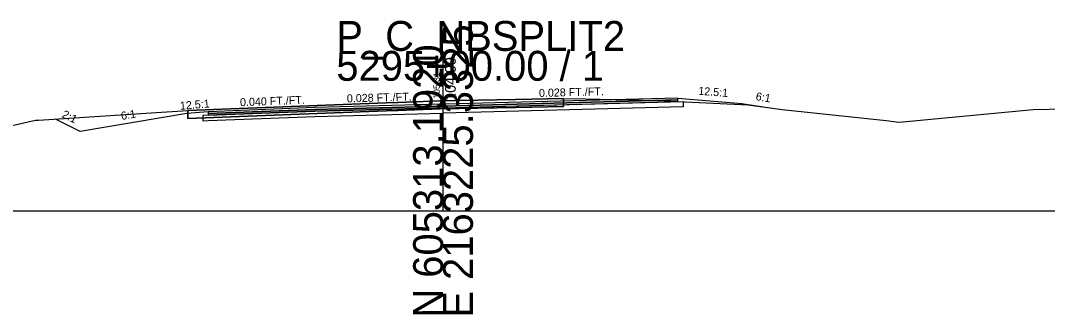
# Model space of a CAD drawing. Extents: x -26 to 1303, y -10 to 12038.
# Drawn here: x 110.4 to 206.6, y 7990.3 to 8017.8 of the extents above; entities that cross this region are included whole.
import ezdxf

# ---------------------------------------------------------------- set-up
doc = ezdxf.new("R2010")
doc.units = 0
for name, color, linetype in [('RD_GPK_XS_Cell', 7, 'Continuous'), ('RD_XS_Base', 7, 'Continuous'), ('RD_XS_ExGround', 7, 'Continuous'), ('RD_XS_ExPaveRet', 7, 'Continuous'), ('RD_XS_Greenside', 7, 'Continuous'), ('RD_XS_Pave', 7, 'Continuous'), ('RD_XS_PaveOvlay_CP', 7, 'Continuous'), ('RD_XS_TieSlope', 7, 'Continuous'), ('RD_XS_TX_Elev_EX', 7, 'Continuous'), ('RD_XS_TX_Elev_PR', 7, 'Continuous'), ('RD_XS_TX_ShdSlope', 7, 'Continuous'), ('RD_XS_TX_Slope', 7, 'Continuous')]:
    doc.layers.add(name, color=color, linetype=linetype)

msp = doc.modelspace()

# ---------------------------------------------------------------- linework, layer by layer
at = {"layer": 'RD_GPK_XS_Cell'}
for p, q in [((150, 8000), (150, 8015)), ((0, 8000), (150, 8000)), ((150, 8000), (300, 8000))]:
    msp.add_line(p, q, dxfattribs=at)
at = {"layer": 'RD_XS_Base'}
for p, q in [((150, 8009.675), (138, 8009.363)), ((150, 8009.675), (172.5, 8010.26)), ((150, 8009.175), (150, 8009.834)), ((150, 8009.834), (150, 8009.834)), ((150, 8009.834), (150, 8009.834)), ((150, 8009.834), (150, 8009.675)), ((172.5, 8009.76), (150, 8009.175)), ((150, 8009.675), (150, 8009.675)), ((150, 8009.175), (150, 8009.675)), ((150, 8009.675), (150, 8009.675)), ((150, 8009.675), (150, 8009.675)), ((172, 8010.247), (172, 8010.247)), ((172, 8010.247), (172, 8010.247)), ((172, 8010.247), (172, 8010.247)), ((172, 8009.747), (172, 8009.747)), ((172, 8009.747), (172, 8009.747)), ((172.5, 8010.26), (172.5, 8009.76)), ((172.5, 8010.227), (172.5, 8010.227)), ((128, 8008.963), (127.5, 8008.943)), ((127.5, 8008.943), (127.5, 8008.943)), ((127.5, 8008.943), (127.5, 8008.443)), ((138, 8009.363), (128, 8008.963)), ((128, 8008.963), (128, 8008.963)), ((128, 8008.463), (138, 8008.863)), ((138, 8009.363), (138, 8009.363)), ((138, 8008.863), (150, 8009.175)), ((138, 8008.863), (138, 8008.863)), ((150, 8009.175), (150, 8009.175)), ((127.5, 8008.443), (128, 8008.463)), ((128, 8008.463), (128, 8008.463))]:
    msp.add_line(p, q, dxfattribs=at)
at = {"layer": 'RD_XS_ExGround'}
msp.add_lwpolyline([(106.167, 8007.217), (111.821, 8008.514), (112.089, 8008.497), (123.111, 8009.221), (124.614, 8009.316), (126.103, 8009.423), (144.682, 8010.133), (145.738, 8010.173), (145.8, 8010.173), (146.591, 8010.201), (149.721, 8010.309), (156.814, 8010.456), (161.286, 8010.541), (163.392, 8010.52), (170.073, 8010.344), (178.592, 8009.952), (181.759, 8009.501), (191.508, 8008.463), (192.706, 8008.335), (193.72, 8008.429), (205.301, 8009.501), (211.3, 8009.648)], dxfattribs=at)
at = {"layer": 'RD_XS_ExPaveRet'}
for points in [[(161.286, 8010.541), (161.286, 8010.541), (161.286, 8009.791), (156.814, 8009.706), (156.814, 8009.706), (149.721, 8009.559), (149.721, 8009.559), (149.721, 8009.559), (146.591, 8009.451), (146.591, 8009.451), (145.8, 8009.423), (145.738, 8009.423), (145.738, 8009.423), (144.682, 8009.383), (144.682, 8009.383), (126.103, 8008.673), (126.103, 8008.673), (126.103, 8009.423), (126.103, 8009.423), (126.103, 8009.423), (144.682, 8010.134), (144.682, 8010.134), (145.738, 8010.173), (145.738, 8010.173), (145.8, 8010.173), (146.591, 8010.201), (146.591, 8010.201), (149.721, 8010.309), (149.721, 8010.309), (149.721, 8010.309), (156.814, 8010.457), (156.814, 8010.457), (161.286, 8010.541)], [(156.814, 8010.457), (149.721, 8010.309), (146.591, 8010.201), (145.8, 8010.173), (145.738, 8010.173), (144.682, 8010.134), (126.103, 8009.423), (126.103, 8008.673), (144.682, 8009.383), (145.738, 8009.423), (145.8, 8009.423), (146.591, 8009.451), (149.721, 8009.559), (156.814, 8009.706), (161.286, 8009.791), (161.286, 8010.541), (156.814, 8010.457)]]:
    msp.add_lwpolyline(points, dxfattribs=at)
at = {"layer": 'RD_XS_Greenside'}
for p, q in [((178, 8010.085), (180.03, 8009.747)), ((126, 8009.121), (116, 8007.454)), ((116, 8007.454), (113.702, 8008.603))]:
    msp.add_line(p, q, dxfattribs=at)
at = {"layer": 'RD_XS_Pave'}
for p, q in [((172, 8010.565), (150, 8009.993)), ((172, 8010.406), (172, 8010.565)), ((172, 8010.565), (172, 8010.565)), ((172, 8010.565), (172, 8010.565)), ((172, 8010.565), (172, 8010.565)), ((138, 8009.681), (128, 8009.281)), ((150, 8009.993), (138, 8009.681)), ((138, 8009.522), (150, 8009.834)), ((150, 8009.834), (138, 8009.522)), ((138, 8009.681), (138, 8009.681)), ((138, 8009.363), (150, 8009.675)), ((172, 8010.406), (150, 8009.834)), ((150, 8009.834), (172, 8010.406)), ((150, 8009.675), (172, 8010.247)), ((150, 8009.993), (150, 8009.993)), ((150, 8009.834), (150, 8009.834)), ((150, 8009.834), (150, 8009.834)), ((150, 8009.834), (150, 8009.675)), ((150, 8009.834), (150, 8009.834)), ((150, 8009.675), (150, 8009.834)), ((150, 8009.834), (150, 8009.834)), ((150, 8009.834), (150, 8009.834)), ((150, 8009.675), (150, 8009.675)), ((150, 8009.675), (150, 8009.675)), ((172, 8010.247), (172, 8010.406)), ((172, 8010.406), (172, 8010.406)), ((172, 8010.406), (172, 8010.406)), ((172, 8010.406), (172, 8010.406)), ((172, 8010.406), (172, 8010.406)), ((172, 8010.406), (172, 8010.406)), ((172, 8010.247), (172, 8010.247)), ((172, 8010.247), (172, 8010.247)), ((128, 8009.122), (138, 8009.522)), ((138, 8009.522), (128, 8009.122)), ((128, 8008.963), (138, 8009.363)), ((128, 8009.281), (128, 8009.281)), ((128, 8009.281), (128, 8009.122)), ((128, 8009.122), (128, 8009.122)), ((128, 8009.122), (128, 8008.963)), ((138, 8009.522), (138, 8009.522)), ((138, 8009.522), (138, 8009.522)), ((138, 8009.363), (138, 8009.363))]:
    msp.add_line(p, q, dxfattribs=at)
at = {"layer": 'RD_XS_PaveOvlay_CP'}
for p, q in [((172, 8010.565), (150, 8009.993)), ((172, 8010.565), (172, 8010.565)), ((172, 8010.565), (172, 8010.565)), ((138, 8009.681), (128, 8009.281)), ((150, 8009.993), (138, 8009.681)), ((138, 8009.681), (138, 8009.681)), ((150, 8009.993), (150, 8009.993))]:
    msp.add_line(p, q, dxfattribs=at)
at = {"layer": 'RD_XS_TieSlope'}
for p, q in [((172, 8010.565), (178, 8010.085)), ((128, 8009.281), (126, 8009.121))]:
    msp.add_line(p, q, dxfattribs=at)

# ---------------------------------------------------------------- texts
at = {"layer": 'RD_GPK_XS_Cell'}
for s, p in [('P_C_NBSPLIT2', (140, 8015)), ('5295+00.00 / 1', (140, 8012.2))]:
    msp.add_text(s, height=2.8, dxfattribs=at).set_placement(p)
for s, p in [('E 2163225.3325', (152.8, 7990)), ('N 605313.1920', (150, 7990))]:
    msp.add_text(s, height=2.8, rotation=90, dxfattribs=at).set_placement(p)
at = {"layer": 'RD_XS_TX_Elev_EX'}
msp.add_text('105.31', height=0.6, rotation=90, dxfattribs=at).set_placement((149.697, 8010.531))
at = {"layer": 'RD_XS_TX_Elev_PR'}
msp.add_text('104.99', height=1, rotation=90, dxfattribs=at).set_placement((151.191, 8010.327))
at = {"layer": 'RD_XS_TX_ShdSlope'}
for rotation, p in [(355.42608, (173.893, 8010.899)), (4.57392, (125.384, 8009.48))]:
    msp.add_text('12.5:1', height=0.75, rotation=rotation, dxfattribs=at).set_placement(p)
at = {"layer": 'RD_XS_TX_Slope'}
for s, rotation, p in [('0.028 FT./FT.', 1.60386, (158.999, 8010.676)), ('0.040 FT./FT.', 2.29061, (130.995, 8009.808)), ('0.028 FT./FT.', 1.60386, (140.999, 8010.172)), ('6:1', 350.53582, (179.257, 8010.393)), ('2:1', 333.43495, (114.229, 8008.81)), ('6:1', 9.46418, (119.893, 8008.528))]:
    msp.add_text(s, height=0.75, rotation=rotation, dxfattribs=at).set_placement(p)

doc.saveas('drawing.dxf')
